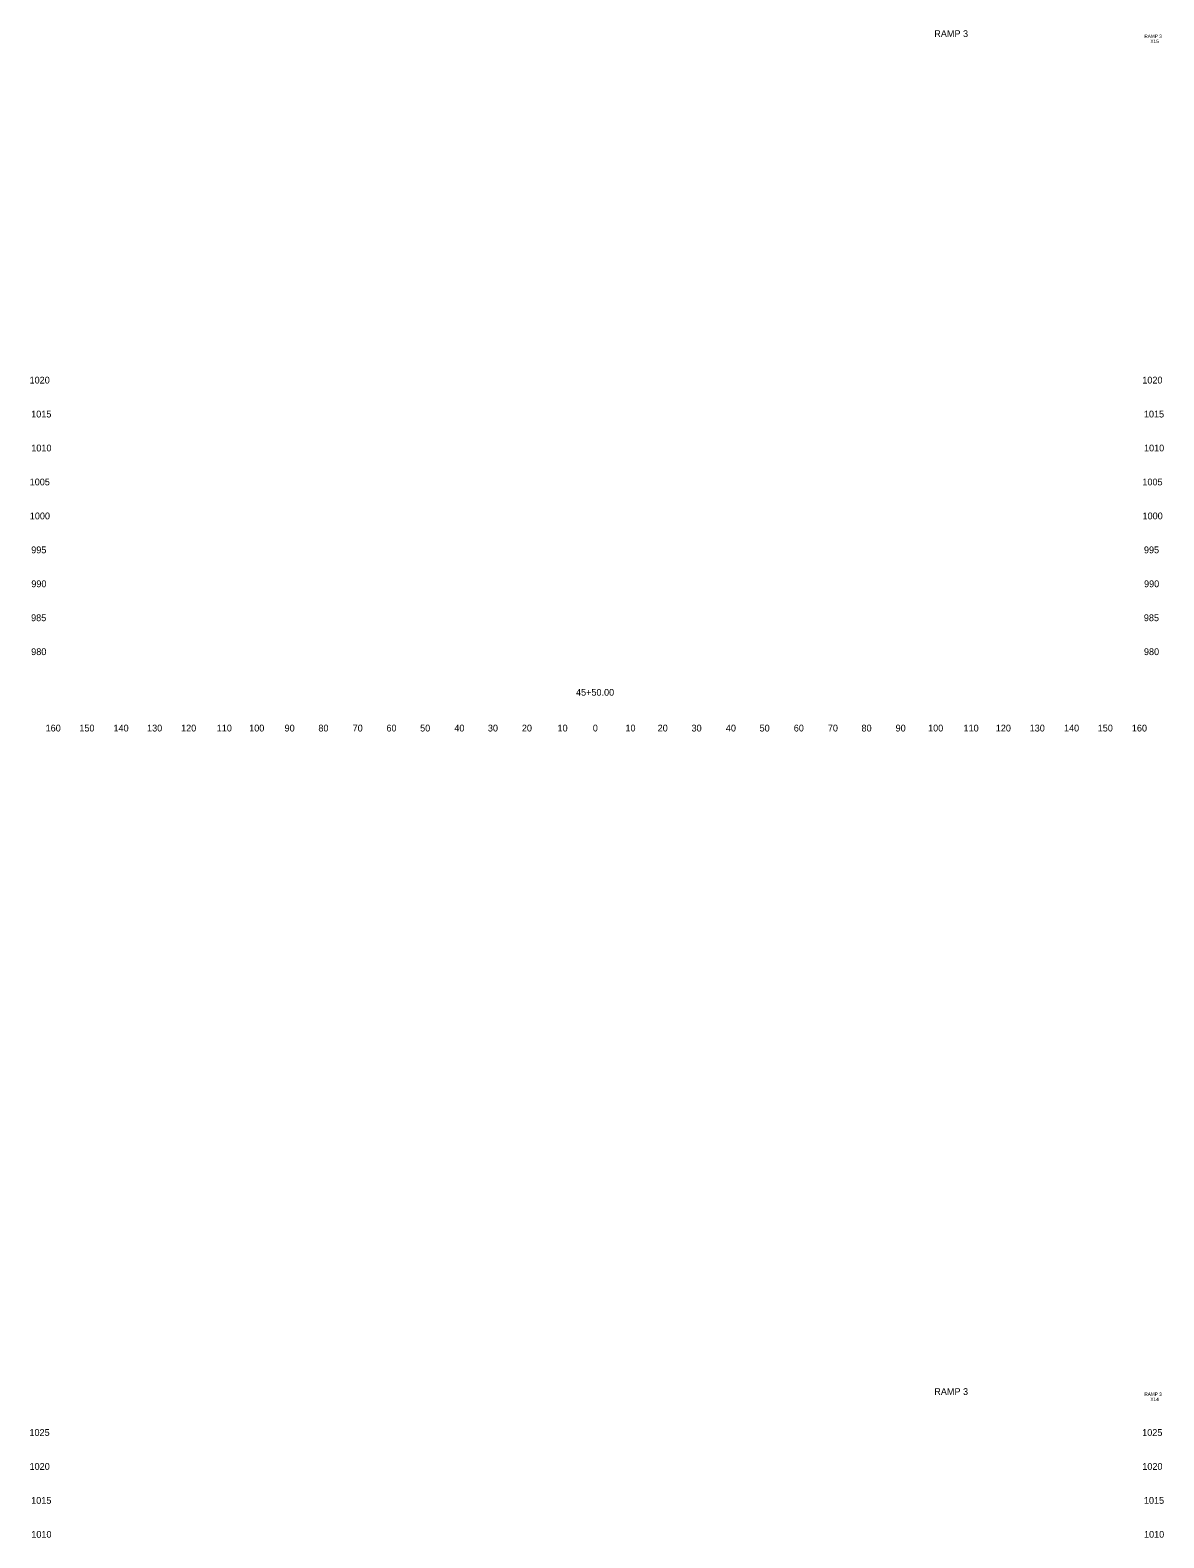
# Model space of a CAD drawing. Extents: x 4994 to 5843, y 4997 to 8804.
# Drawn here: x 5508.5 to 5842.5, y 6360 to 6804.1 of the extents above; entities that cross this region are included whole.
import ezdxf

# ---------------------------------------------------------------- set-up
doc = ezdxf.new("R2010")
doc.units = 0
for name, color, linetype in [('RD_SHT_ID', 7, 'Continuous'), ('RD_XS_TX_Offset', 7, 'Continuous'), ('RD_XS_TX_Station', 7, 'Continuous')]:
    doc.layers.add(name, color=color, linetype=linetype)

msp = doc.modelspace()

# ---------------------------------------------------------------- texts
at = {"layer": 'RD_SHT_ID'}
for s, height, p in [('RAMP 3', 2, (5774.89, 6802.06)), ('RAMP 3', 1, (5836.78, 6801.8)), ('X15', 1, (5838.57, 6800.3)), ('RAMP 3', 2, (5774.89, 6402.06)), ('RAMP 3', 1, (5836.78, 6401.8)), ('X14', 1, (5838.57, 6400.3))]:
    msp.add_text(s, height=height, dxfattribs=at).set_placement(p)
at = {"layer": 'RD_XS_TX_Offset'}
for s, p in [('1020', (5508.37, 6700)), ('1020', (5836.17, 6700)), ('1015', (5508.85, 6690)), ('1015', (5836.65, 6690)), ('1010', (5508.88, 6680)), ('1010', (5836.68, 6680)), ('1005', (5508.4, 6670)), ('1005', (5836.2, 6670)), ('1000', (5508.44, 6660)), ('1000', (5836.24, 6660)), ('995', (5508.86, 6650)), ('995', (5836.66, 6650)), ('990', (5508.89, 6640)), ('990', (5836.69, 6640)), ('985', (5508.83, 6630)), ('985', (5836.63, 6630)), ('980', (5508.86, 6620)), ('980', (5836.66, 6620)), ('160', (5513.1, 6597.5)), ('150', (5523.04, 6597.5)), ('140', (5533.1, 6597.5)), ('130', (5542.99, 6597.5)), ('120', (5553.01, 6597.5)), ('110', (5563.51, 6597.5)), ('100', (5573.07, 6597.5)), ('90', (5583.5, 6597.5)), ('80', (5593.46, 6597.5)), ('70', (5603.54, 6597.5)), ('60', (5613.5, 6597.5)), ('50', (5623.43, 6597.5)), ('40', (5633.5, 6597.5)), ('30', (5643.39, 6597.5)), ('20', (5653.4, 6597.5)), ('10', (5663.91, 6597.5)), ('0', (5674.3, 6597.5)), ('0', (5674.3, 6597.5)), ('10', (5683.91, 6597.5)), ('20', (5693.4, 6597.5)), ('30', (5703.39, 6597.5)), ('40', (5713.5, 6597.5)), ('50', (5723.43, 6597.5)), ('60', (5733.5, 6597.5)), ('70', (5743.54, 6597.5)), ('80', (5753.46, 6597.5)), ('90', (5763.5, 6597.5)), ('100', (5773.07, 6597.5)), ('110', (5783.51, 6597.5)), ('120', (5793.01, 6597.5)), ('130', (5802.99, 6597.5)), ('140', (5813.1, 6597.5)), ('150', (5823.04, 6597.5)), ('160', (5833.1, 6597.5)), ('1025', (5508.34, 6390)), ('1025', (5836.14, 6390)), ('1020', (5508.37, 6380)), ('1020', (5836.17, 6380)), ('1015', (5508.85, 6370)), ('1015', (5836.65, 6370)), ('1010', (5508.88, 6360)), ('1010', (5836.68, 6360))]:
    msp.add_text(s, height=2, dxfattribs=at).set_placement(p)
at = {"layer": 'RD_XS_TX_Station'}
msp.add_text('45+50.00', height=2, dxfattribs=at).set_placement((5669.35, 6608.04))

doc.saveas('drawing.dxf')
